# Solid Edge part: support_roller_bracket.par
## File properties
Title: Support roller bracket
Author: Abhinav Rai
Template: Normal.par
Last saved by: SOFT
Revision: 24
Application: Solid Edge
Accuracy: 0.99
Material: aluminum
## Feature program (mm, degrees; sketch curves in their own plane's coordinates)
sketch for "unnamed Protrusion 1" #1 plane through (0, 0, 0) normal (0, -1, 0) x-axis (1, 0, 0)
  circle centre (0, -138.9237) radius 3.81
sketch for "unnamed Protrusion 1" #2 plane through (0, 0, 0) normal (0, -1, 0) x-axis (1, 0, 0)
  line (143.637, -99.9249) -> (-143.637, -99.9249)
  line (-143.637, -99.9249) -> (-143.637, -115.1647)
  line (-143.637, -115.1647) -> (-61.0846, -156.7704)
  line (-61.0846, -156.7704) -> (-61.0846, -162.9363)
  line (-61.0846, -162.9363) -> (61.0846, -162.9363)
  line (61.0846, -156.7704) -> (61.0846, -162.9363)
  line (143.637, -115.1647) -> (61.0846, -156.7704)
  line (143.637, -99.9249) -> (143.637, -115.1647)
  dimension (linear) = 143.637
extrude "unnamed Protrusion 1" add finite 101.6 symmetric
fillet "Round_1" radius 31.75
fillet "Round_2" radius 6.35
sketch for "unnamed Protrusion 2" plane through (0, 0, 67.2512) normal (1, 0, 0) x-axis (0, 1, 0)
  arc centre (-23.4135, -61.792) radius 19.05 from (-23.4135, -42.742) to (-42.405, -60.3002) ccw
  line (-50.8, -167.1761) -> (-42.405, -60.3002)
  line (-50.8, -167.1761) -> (50.8, -167.1761)
  line (45.7777, -60.8928) -> (50.8, -167.1761)
  arc centre (26.749, -61.792) radius 19.05 from (26.749, -42.742) to (45.7777, -60.8928) cw
  line (19.05, -42.742) -> (26.749, -42.742)
  line (19.05, -64.967) -> (19.05, -42.742)
  arc centre (0, -64.967) radius 19.05 from (-19.05, -64.967) to (19.05, -64.967) ccw
  line (-19.05, -42.742) -> (-19.05, -64.967)
  line (-23.4135, -42.742) -> (-19.05, -42.742)
extrude "unnamed Protrusion 2" add to key point symmetric
sketch for "ExtrudedCutout_1" plane through (0, 0, 0) normal (0, -1, 0) x-axis (1, 0, 0)
  line (-128.3193, 24.5092) -> (125.6319, 24.5092)
  line (125.6319, 24.5092) -> (125.6319, -99.9249)
  line (125.6319, -99.9249) -> (-128.3193, -99.9249)
  line (-128.3193, -99.9249) -> (-128.3193, 24.5092)
extrude "ExtrudedCutout_1" cut finite 203.2 symmetric
chamfer "Chamfer_1" setback 5.08
rib "Rib_1"  Thickness = 25.4 mm
mirror "unnamed Mirror 1" of "Rib_1" about plane through (0, 0, 0) normal (1, 0, 0)
rib "unnamed Rib 1"
sketch for "Hole_1" plane through (0.1259, 0, -162.9363) normal (0, 0, -1) x-axis (-1, 0, 0)
  hole centre (0.1259, 0) bore radius 25.4
hole "Hole_1" diameter 50.8 through
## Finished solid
Body 1: solid body, 55 faces, 142 edges, 86 vertices.
  Faces by surface: plane 38, cylinder 17
  Edges by curve: line 106, circle 34, intersection 2
Bounding box of the edges (mm): 379.121 x 101.600 x 187.446, from (-189.5605, -50.8, -162.9363) to (189.5605, 50.8, 24.5092).
Cylindrical faces by radius (mm): R3.81 x2, R6.35 x2, R19.05 x6, R25.4 x1, R31.75 x4, R55.372 x2
Planar faces by outward normal: +x 4, +y 5, +z 5, -x 4, -y 5, -z 1, oblique 14
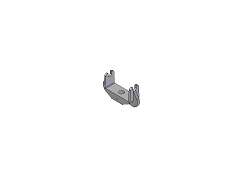
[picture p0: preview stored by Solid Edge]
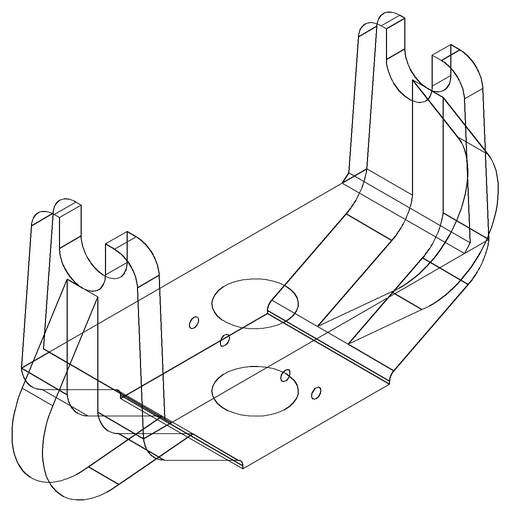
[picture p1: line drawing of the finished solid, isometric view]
